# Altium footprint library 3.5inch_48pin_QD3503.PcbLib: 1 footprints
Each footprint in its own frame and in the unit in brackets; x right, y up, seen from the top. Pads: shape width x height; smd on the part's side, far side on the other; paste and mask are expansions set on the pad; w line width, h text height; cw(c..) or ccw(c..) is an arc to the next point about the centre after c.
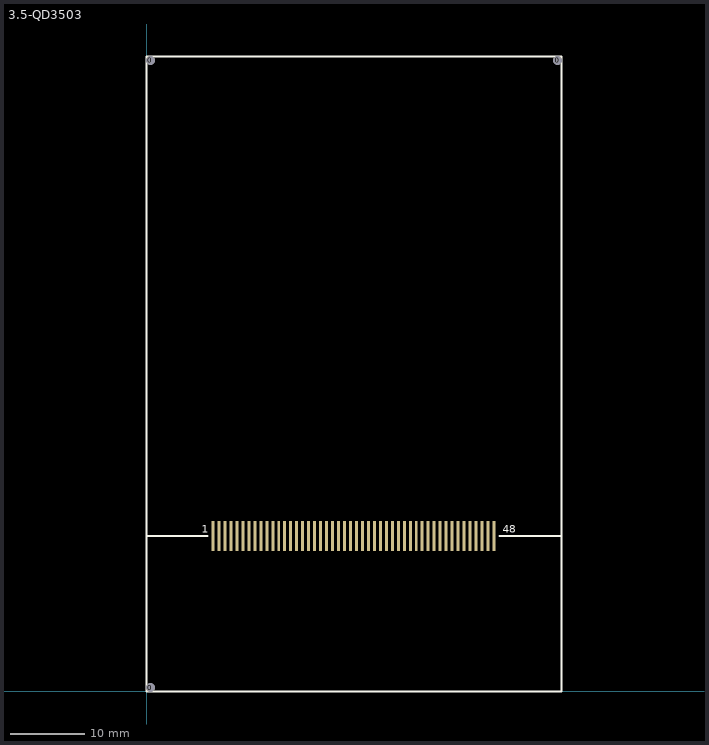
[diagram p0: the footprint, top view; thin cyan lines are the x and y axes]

## 3.5-QD3503 [mm] "3.5 TFT LCD"
pads (51):
  round 1.2 hole 1.2 unplated: 0(0.5,0.5) 0(0.5,84.46) 0(55,84.46)
  rect 0.4x4 smd: 1(8.88,20.8) 2(9.68,20.8) 3(10.48,20.8) 4(11.28,20.8) 5(12.08,20.8) 6(12.88,20.8) 7(13.68,20.8) 8(14.48,20.8) 9(15.28,20.8) 10(16.08,20.8) 11(16.88,20.8) 12(17.68,20.8) 13(18.48,20.8) 14(19.28,20.8) 15(20.08,20.8) 16(20.88,20.8) 17(21.68,20.8) 18(22.48,20.8) 19(23.28,20.8) 20(24.08,20.8) 21(24.88,20.8) 22(25.68,20.8) 23(26.48,20.8) 24(27.28,20.8) 25(28.08,20.8) 26(28.88,20.8) 27(29.68,20.8) 28(30.48,20.8) 29(31.28,20.8) 30(32.08,20.8) 31(32.88,20.8) 32(33.68,20.8) 33(34.48,20.8) 34(35.28,20.8) 35(36.08,20.8) 36(36.88,20.8) 37(37.68,20.8) 38(38.48,20.8) 39(39.28,20.8) 40(40.08,20.8) 41(40.88,20.8) 42(41.68,20.8) 43(42.48,20.8) 44(43.28,20.8) 45(44.08,20.8) 46(44.88,20.8) 47(45.68,20.8) 48(46.48,20.8)
Top Overlay:
  lines w0.254: 0.028,20.8 8.128,20.8 ; 47.232,20.8 55.5,20.8 ; 0,0 0,84.96 55.5,84.96 55.5,0 0,0
  text "48" at 47.625,21.209 h1.02
  text "1" at 7.366,21.209 h1.02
